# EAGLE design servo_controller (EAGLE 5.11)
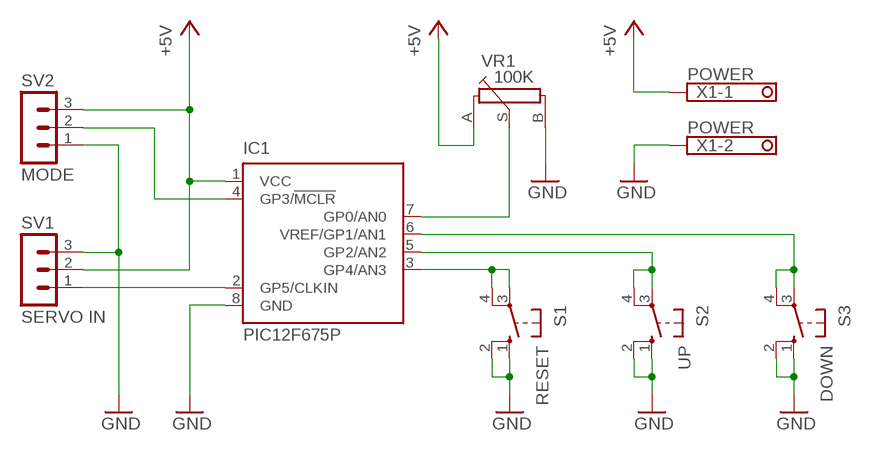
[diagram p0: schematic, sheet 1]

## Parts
IC1  PIC12F675P  [DIL8]
S1  RESET  10-XX  [B3F-10XX]
S2  UP  10-XX  [B3F-10XX]
S3  DOWN  10-XX  [B3F-10XX]
SV1  SERVO IN  MA03-1  [MA03-1]
SV2  MODE  MA03-1  [MA03-1]
VR1  100K  CHPOT1  [POT_B1]
X1  POWER  1751248  [1751248]

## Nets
+5V: IC1.1(VCC) SV1.2 SV2.3 VR1.A X1.1
GND: IC1.8(GND) S1.1(S) S1.2(S1) S2.1(S) S2.2(S1) S3.1(S) S3.2(S1) SV1.3 SV2.1 VR1.B X1.2
N$1: IC1.2(GP5/CLKIN) SV1.1
N$2: IC1.7(GP0/AN0) VR1.S
N$5: IC1.3(GP4/AN3) S1.3(P) S1.4(P1)
N$7: IC1.5(GP2/AN2) S2.3(P) S2.4(P1)
N$9: IC1.6(VREF/GP1/AN1) S3.3(P) S3.4(P1)
N$11: IC1.4(GP3/!MCLR) SV2.2

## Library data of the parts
IC1 = microchip:PIC12F675: 8-Pin FLASH-Based 8-Bit CMOS Microcontroller Precision Internal 4 MHz oscillator factory calibrated to ±1% Low Power Features: Standby Current: - 1 nA @ 2.0V, typical Operating Current: - 8.5&micro;A @ 32 kHz, 2.0V, typical - 100&micro;A @ 1 MHz, 2.0V, typical Watchdog Timer Current: - 300 nA @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; MF: MICROCHIP; MPN: PIC12F675-E/P; OC_FARNELL: 9759018; OC_NEWARK: 92C4340
S1-S3 = switch-omron:10-XX: OMRON SWITCH; MPN: B3F-1000; OC_FARNELL: 176432; OC_NEWARK: 36M3542
SV1 SV2 = con-lstb:MA03-1: PIN HEADER; OC_FARNELL: unknown; OC_NEWARK: unknown
VR1 = nano_control_02042011:CHPOT1: Standard Potentiometer B
X1 = con-phoenix-350:1751248: MKDS 1/ 2-3,5 Printklemme; OC_FARNELL: unknown; OC_NEWARK: unknown

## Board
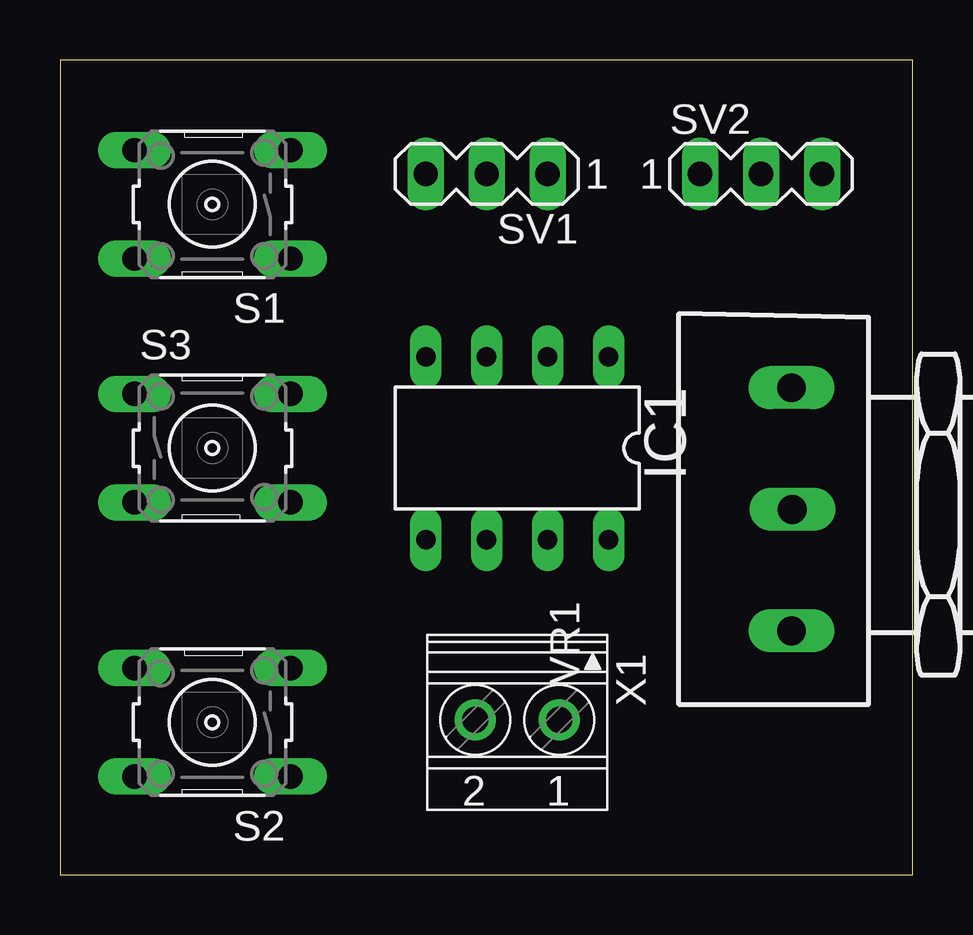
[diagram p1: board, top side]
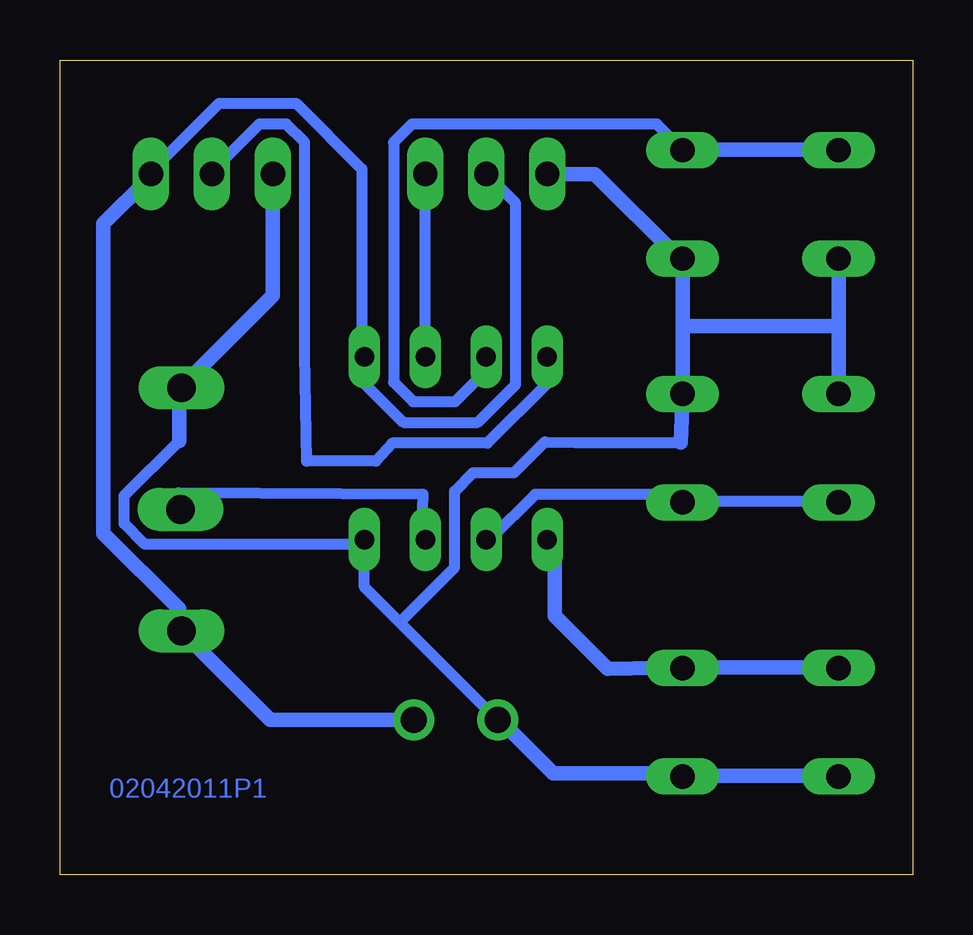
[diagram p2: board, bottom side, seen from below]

Size 35.54 x 33.96 mm. Coordinates in mm from the lower left corner, seen from the top.
Outline: 0,0 35.54,0 35.54,33.96 0,33.96 0,0
Copper layers (1*16): Top 0.035mm / dielectric 1.5mm / Bottom 0.035mm
Design rules "default *": minimum track width 18mil, minimum drill 24mil, track to track 16mil, track to pad 12mil, pad to pad 12mil, via to via 12mil, smd to smd 8mil, copper to edge 40mil, drill to drill 8mil, minimum pad ring 10mil, minimum via ring 8mil, stop-mask expansion 4mil, vias tented up to drill 0mil, thermal gap 10mil

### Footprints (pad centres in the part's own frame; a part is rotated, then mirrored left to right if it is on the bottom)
DIL8 = drill 0.813 long: 1 -3.81,-3.81; 2 -1.27,-3.81; 3 1.27,-3.81; 4 3.81,-3.81; 5 3.81,3.81; 6 1.27,3.81; 7 -1.27,3.81; 8 -3.81,3.81
B3F-10XX = drill 1.016 long: 1 -3.251,2.261; 2 3.251,2.261; 3 -3.251,-2.261; 4 3.251,-2.261
MA03-1 = drill 1.016 long: 1 -2.54,0; 2 0,0; 3 2.54,0
POT_B1 = drill 1.2 long: A 0,0; B 10.136,0; S 5.062,-0.035
1751248 = drill 1.1 pad 1.7 round: 1 -1.75,-0.1; 2 1.75,-0.1

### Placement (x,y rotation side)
IC1  19.05,17.78 180 top
S1  6.35,27.94 180 top
S2  6.35,6.35 180 top
S3  6.35,17.78 0 top
SV1  17.78,29.21 180 top
SV2  29.21,29.21 0 top
VR1  30.48,10.16 90 top
X1  19.05,6.35 180 top

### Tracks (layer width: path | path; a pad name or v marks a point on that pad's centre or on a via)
+5V
  Bottom 0.457: X1.1 20.83,6.45 | SV1.2 16.56,27.99 16.56,20.42 18.14,18.85 21.23,18.85 22.86,20.47 IC1.1 22.96,21.79 22.96,29.41 25.7,32.16 28.91,32.16 31.75,29.31 SV2.3 31.85,29.01 | VR1.A 30.58,10.36
  Bottom 0.61: 20.83,6.45 26.77,6.45 VR1.A | 30.58,10.36 30.58,11.07 33.73,14.22 33.73,27.13 31.85,29.01
GND
  Bottom 0.457: S1.1 9.8,25.76 | 30.48,20.32 VR1.B 30.58,20.12 | S2.2 3.1,4.11 | 9.6,4.11 S2.1 9.8,4.22 | 21.39,10.52 17.32,6.45 X1.2 17.12,6.35 | 21.39,10.52 22.86,11.99 IC1.8 23.06,13.77 32,13.77 32.87,14.63 32.87,15.8 30.58,18.08 | 9.68,18.01 14.05,18.01 15.34,18.03 16.62,16.75 18.32,16.75 19.1,15.97 19.1,12.8 21.39,10.52
  Bottom 0.61: 3.1,22.86 S3.1 | 3.1,22.86 S1.2 | 9.6,22.86 S3.2 9.68,18.01 | 9.6,22.86 S1.1 | SV1.3 13.26,29.21 9.8,25.76 | 9.6,22.86 3.1,22.86 | SV2.1 26.67,24.13 30.48,20.32 | 3.1,4.11 9.6,4.11 | 9.8,4.22 14.99,4.22 17.12,6.35 | 30.58,18.08 30.58,20.12
N$1
  Bottom 0.457: IC1.2 SV1.1
N$2
  Bottom 0.457: IC1.7 20.47,13.97 20.41,15.85 30.6,15.91 30.48,15.24 VR1.S
N$5
  Bottom 0.457: IC1.3 17.93,21.59 17.96,20.6 18.2,20.6 19.08,19.71 20.83,19.71 21.64,20.52 21.64,30.53 20.88,31.29 10.67,31.29 9.6,30.23 S1.3 9.4,30.23 | S1.4 3.1,30.23
  Bottom 0.61: 3.1,30.23 9.4,30.23
N$7
  Bottom 0.457: 14.93,13.97 IC1.5 | 9.6,8.64 S2.3 9.4,8.64 | S2.4 3.1,8.64
  Bottom 0.61: 9.6,8.64 12.72,8.58 14.93,10.79 14.93,13.97 | 3.1,8.64 9.4,8.64
N$9
  Bottom 0.457: IC1.6 17.63,13.97 15.75,15.85 9.91,15.85 9.6,15.54 S3.4 9.4,15.54 3.1,15.54 S3.3
N$11
  Bottom 0.457: IC1.4 15.24,20.47 17.73,17.98 21.7,17.98 22.38,17.24 25.27,17.24 25.35,21.69 25.35,30.53 26.11,31.29 27.23,31.29 29.21,29.31 SV2.2

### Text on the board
Bottom: 02042011P1
tValues: 02042011P1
